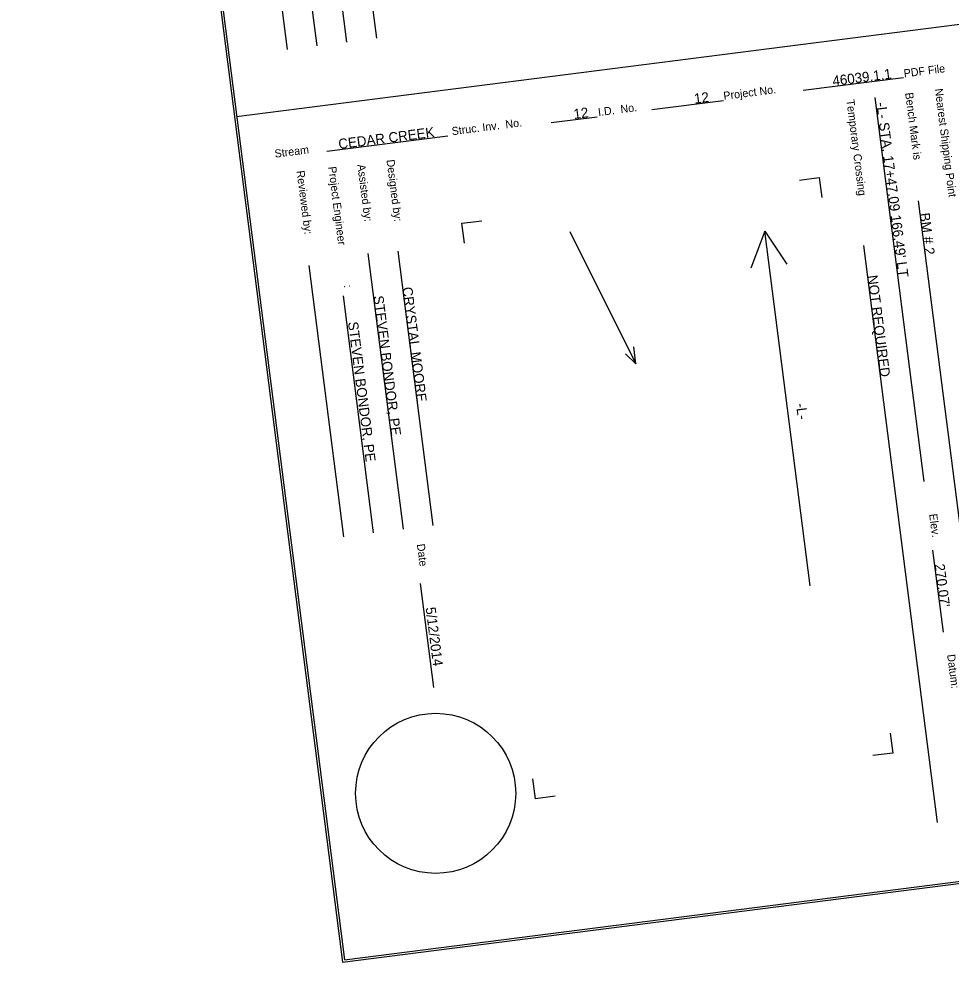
# Model space of a CAD drawing. Extents: x 2166991 to 2168450, y 842134 to 844444.
# Drawn here: x 2166991.4 to 2167457.3, y 842678.7 to 843150.2 of the extents above; entities that cross this region are included whole.
import ezdxf

# ---------------------------------------------------------------- set-up
doc = ezdxf.new("R2010")
doc.units = 0
for name, color, linetype in [('Exist Plan Preparation Drainage Notes Label', 7, 'Continuous'), ('Prop Drainage Structure Plot Symbol 20 Scale', 7, 'Continuous'), ('Prop Erosion Embankment Toe Protection with Rip Rap 3 Detail CELL', 7, 'Continuous'), ('Prop Plan Preparation Watershed Post Construction', 7, 'Continuous')]:
    doc.layers.add(name, color=color, linetype=linetype)

msp = doc.modelspace()

# ---------------------------------------------------------------- linework, layer by layer
at = {"layer": 'Exist Plan Preparation Drainage Notes Label'}
for p, q in [((2167125.59, 843134.8), (2167094.16, 843380.82)), ((2167140.47, 843136.7), (2167131.47, 843207.14)), ((2167170.22, 843140.5), (2167162, 843204.85)), ((2167155.34, 843138.6), (2167147.8, 843197.7)), ((2167100.22, 843101.38), (2167645.78, 843171.06)), ((2167383.33, 843114.5), (2167433.45, 843120.91)), ((2167307.67, 843104.86), (2167343.5, 843109.43)), ((2167419.09, 843110.89), (2167443.62, 842918.85)), ((2167257.33, 843098.33), (2167280.43, 843101.28)), ((2167145.22, 843084.01), (2167205.85, 843091.76)), ((2167381.44, 843069.57), (2167391.36, 843070.84)), ((2167391.36, 843070.84), (2167392.62, 843060.92)), ((2167440.83, 843059.14), (2167480.03, 842752.21)), ((2167212.81, 843048.04), (2167222.73, 843049.3)), ((2167214.07, 843038.12), (2167212.81, 843048.04)), ((2167413.43, 843036.88), (2167450.27, 842748.4)), ((2167165.79, 843032.93), (2167183.4, 842895.1)), ((2167180.77, 843034.04), (2167198.28, 842897)), ((2167136.32, 843026.86), (2167153.64, 842891.3)), ((2167153.39, 843011.65), (2167168.52, 842893.2)), ((2167448, 842884.62), (2167453.24, 842843.59)), ((2167191.96, 842867.86), (2167198.59, 842815.99)), ((2167426.83, 842793.1), (2167428.1, 842783.18)), ((2167428.1, 842783.18), (2167418.18, 842781.91)), ((2167249.55, 842760.37), (2167248.28, 842770.29)), ((2167259.47, 842761.64), (2167249.55, 842760.37))]:
    msp.add_line(p, q, dxfattribs=at)
msp.add_lwpolyline([(2166992.52, 843944.53), (2167154.06, 842679.8), (2168245.2, 842819.17), (2168083.66, 844083.9)], close=True, dxfattribs=at)
msp.add_circle((2167199.68, 842763.05), 40, dxfattribs=at)
at = {"layer": 'Prop Drainage Structure Plot Symbol 20 Scale'}
for p, q in [((2167364.14, 843044.08), (2167357.17, 843025.57)), ((2167299.79, 842977.75), (2167294.54, 842982.82))]:
    msp.add_line(p, q, dxfattribs=at)
for points in [[(2167266.81, 843043.83), (2167299.79, 842977.75), (2167298.7, 842986.29)], [(2167386.79, 842866.75), (2167364.14, 843044.08), (2167375.24, 843027.53)]]:
    msp.add_lwpolyline(points, dxfattribs=at)
at = {"layer": 'Prop Plan Preparation Watershed Post Construction'}
msp.add_lwpolyline([(2168246.32, 842818.31), (2168084.52, 844085.01), (2166991.4, 843945.39), (2167153.2, 842678.68)], close=True, dxfattribs=at)

# ---------------------------------------------------------------- texts
at = {"layer": 'Exist Plan Preparation Drainage Notes Label'}
for s, rotation, p in [('PDF File', 7.279, (2167433.84, 843120.91)), ('Project No.', 7.279, (2167343.74, 843109.67)), ('Bench Mark is', 277.279, (2167434.28, 843113.13)), ('Nearest Shipping Point', 277.279, (2167449.14, 843115.12)), ('I.D.  No.', 7.279, (2167281.08, 843101.56)), ('Temporary Crossing', 277.279, (2167404.91, 843109.62)), ('Struc. Inv.  No.', 7.279, (2167207.94, 843092)), ('Stream', 7.279, (2167119.46, 843080.77)), ('Designed by:', 277.279, (2167175.11, 843079.61)), ('Project Engineer', 277.279, (2167146.01, 843076.14)), ('Assisted by:', 277.279, (2167160.52, 843077.23)), ('Reviewed by:', 277.279, (2167130.13, 843074.11)), (':', 277.279, (2167153.79, 843017.02)), ('Elev.', 277.279, (2167446.29, 842902.57)), ('Date', 277.279, (2167190.27, 842887.54)), ('Datum:', 277.279, (2167455.27, 842832.32))]:
    msp.add_text(s, height=4, rotation=rotation, dxfattribs=at).set_placement(p)
at = {"layer": 'Prop Drainage Structure Plot Symbol 20 Scale'}
msp.add_text('-L-', height=5, rotation=277.279, dxfattribs=at).set_placement((2167379.73, 842957.73))
at = {"layer": 'Prop Erosion Embankment Toe Protection with Rip Rap 3 Detail CELL'}
for s, rotation, p in [('46039.1.1', 7.279, (2167398.31, 843116.61)), ('12', 7.279, (2167329.16, 843107.77)), ("-L- STA. 17+47.09 166.49' LT", 277.279, (2167419.91, 843108.12)), ('12', 7.279, (2167268.91, 843100.08)), ('CEDAR CREEK', 7.279, (2167151.4, 843085.07)), ('BM # 2 ', 277.279, (2167441.53, 843052.93)), ('NOT REQUIRED', 277.279, (2167415.45, 843021.77)), ('CRYSTAL MOORE', 277.279, (2167183, 843015.87)), ('STEVEN BONDOR, PE', 277.279, (2167168.56, 843011.53)), ('STEVEN BONDOR, PE', 277.279, (2167155.86, 842998.51)), ("270.07'", 277.279, (2167449.03, 842877.45)), ('5/12/2014', 277.279, (2167194.66, 842855.84))]:
    msp.add_text(s, height=5, rotation=rotation, dxfattribs=at).set_placement(p)

doc.saveas('drawing.dxf')
